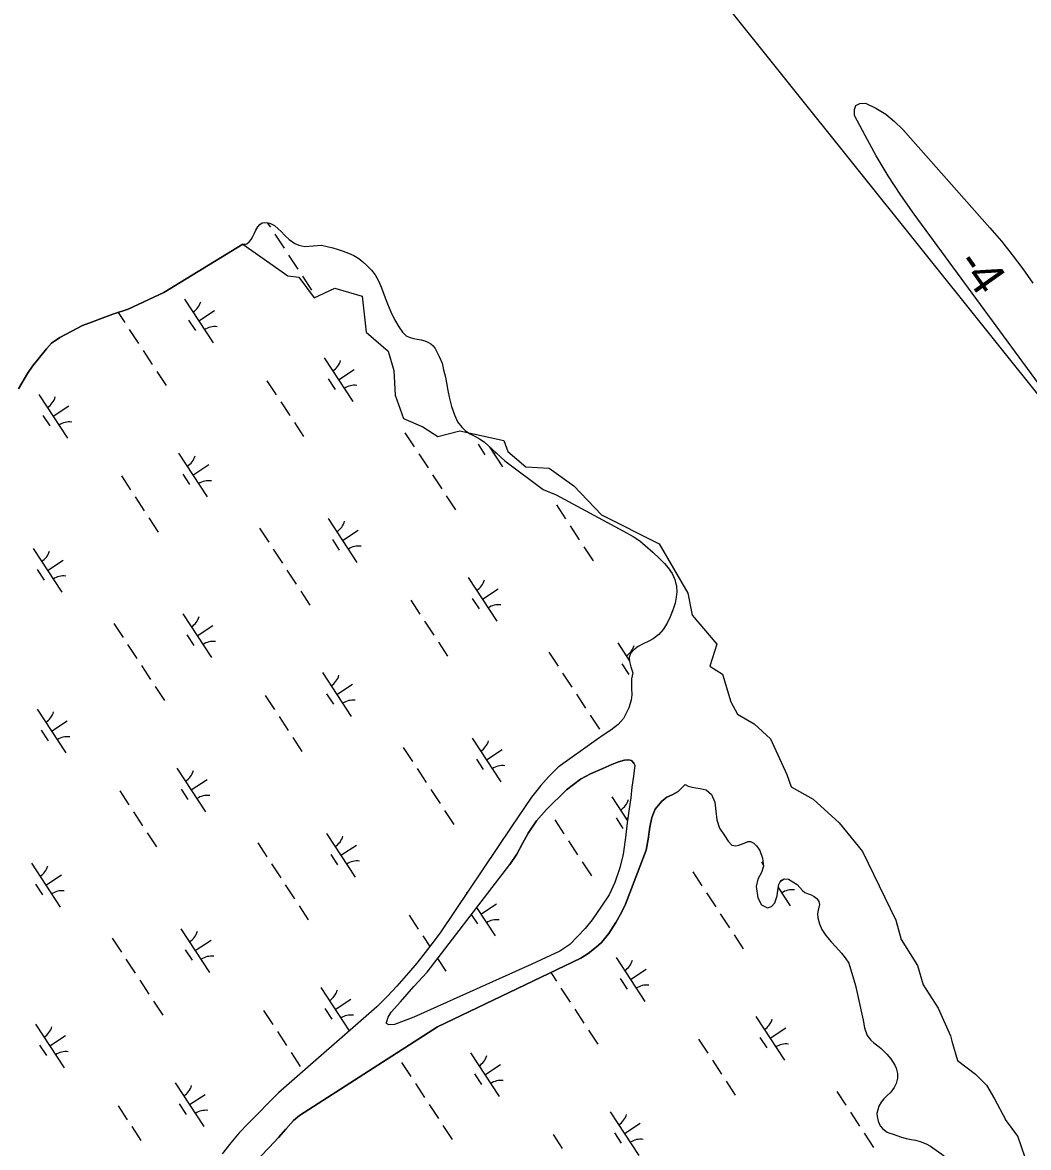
# Model space of a CAD drawing. Extents: x 3945642 to 3966284, y 206476 to 228921.
# Drawn here: x 3955515 to 3956476, y 216052 to 217128 of the extents above; entities that cross this region are included whole.
import ezdxf

# ---------------------------------------------------------------- set-up
doc = ezdxf.new("R2010")
doc.units = 0
for name, color, linetype in [('V-RIVR-EDGE', 7, 'Continuous'), ('V-RIVR-RANG', 7, 'Continuous'), ('V-TOPO-DPTH', 7, 'Continuous'), ('V-TOPO-MINR', 7, 'Continuous'), ('V-TOPO-SHOR', 7, 'Continuous'), ('V-WETL-SWMP', 7, 'Continuous')]:
    doc.layers.add(name, color=color, linetype=linetype)

msp = doc.modelspace()

# ---------------------------------------------------------------- linework, layer by layer
at = {"layer": 'V-RIVR-EDGE'}
for points in [[(3955725.2, 216916), (3955768.4, 216885.7), (3955768.4, 216885.7), (3955778.9, 216884.4), (3955793.4, 216864.6), (3955813.1, 216873.8), (3955839.4, 216866), (3955843.3, 216831.8), (3955864.3, 216813.4), (3955869.6, 216795), (3955870.9, 216771.3), (3955878.8, 216749), (3955897.2, 216741.1), (3955911.6, 216731.9), (3955932.7, 216737.2), (3955974.7, 216728), (3955978.7, 216717.5), (3955995.7, 216703), (3956018.1, 216701.7), (3956041.7, 216684.6), (3956068, 216657), (3956123.2, 216629.4), (3956150.8, 216582.1), (3956154.8, 216561.1), (3956178.4, 216533.5), (3956171.8, 216512.4), (3956183.7, 216504.6), (3956191.6, 216478.3), (3956198.1, 216466.4), (3956213.9, 216457.2), (3956229.7, 216442.8), (3956245.4, 216408.6), (3956249.4, 216396.8), (3956270.4, 216385), (3956295.4, 216362.6), (3956317.7, 216335), (3956349.3, 216269.3), (3956354.5, 216250.9), (3956370.3, 216226), (3956375.5, 216207.6), (3956390, 216185.2), (3956401.8, 216158.9), (3956403.1, 216153.7), (3956408.4, 216135.3), (3956425.5, 216122.1), (3956436, 216111.6), (3956443.9, 216098.5), (3956454.4, 216078.8)], [(3956509.6, 216035.4), (3956497, 216017.5), (3956489.8, 216000.7), (3956480.3, 216001.9), (3956468.4, 215999.6), (3956460, 215994.8), (3956476.7, 216019.8), (3956473.1, 216042.5), (3956466, 216062.8), (3956454.4, 216078.8)]]:
    msp.add_lwpolyline(points, dxfattribs=at)
at = {"layer": 'V-TOPO-DPTH'}
msp.add_line((3957463.9, 215548.9), (3955413.9, 218111.3), dxfattribs=at)
at = {"layer": 'V-TOPO-MINR'}
msp.add_lwpolyline([(3956690.9, 216503), (3956367, 216944.4), (3956354.3, 216962.6), (3956342.1, 216981.1), (3956330.8, 217000.2), (3956320.1, 217019.6), (3956310, 217039), (3956309.8, 217044.5), (3956311.2, 217048.5), (3956315, 217050.3), (3956320.4, 217050.6), (3956330.4, 217045.8), (3956339.8, 217040.1), (3956348.3, 217033.2), (3956356.3, 217025.4), (3956439.4, 216931.5), (3956450.3, 216918.8), (3956460.8, 216905.7), (3956470.8, 216892.3), (3956480.5, 216878.7)], dxfattribs=at)
at = {"layer": 'V-TOPO-SHOR'}
for points in [[(3955725.2, 216916), (3955649.9, 216869.6), (3955615.7, 216853.6), (3955601, 216848.8), (3955588.4, 216844.2), (3955581.6, 216841.7), (3955571.9, 216838.2), (3955550.4, 216826.6), (3955542.5, 216821.2), (3955537.6, 216815.8), (3955524.4, 216799.1), (3955519.6, 216792.2), (3955510.8, 216777.6)], [(3956098.1, 216505.8), (3956096.9, 216500.2), (3956096.9, 216491.2), (3956097.1, 216484.8), (3956096.4, 216479.7), (3956094.4, 216472.5), (3956089.2, 216462.4), (3956084.1, 216456.6), (3956077.1, 216451.1), (3956070.7, 216447), (3956063.4, 216441.9), (3956026.8, 216415.6), (3956017.9, 216406.8), (3956010.1, 216398.3), (3956001.2, 216387.1), (3955981.8, 216358.2), (3955914.5, 216258.4), (3955909.2, 216251), (3955899.7, 216238.4), (3955891.7, 216228.2), (3955883.8, 216219.1), (3955872.4, 216206.2), (3955863.5, 216196.8), (3955853.3, 216186.6), (3955759.4, 216104.4), (3955730.3, 216074.9), (3955721.7, 216066), (3955713.9, 216056.6), (3955705.4, 216046.1)], [(3956099.9, 216417.7), (3956098.7, 216407.1), (3956097.2, 216396.6), (3956096.1, 216386.4), (3956094.7, 216376), (3956092.8, 216362.4), (3956091, 216348.5), (3956088.8, 216332.5), (3956085.7, 216319.4), (3956081, 216305.3), (3956075.6, 216293.6), (3956067.4, 216281.7), (3956059.1, 216269.6), (3956052.6, 216261.5), (3956037.7, 216246.3), (3956028.3, 216239.8), (3956001.4, 216227.5), (3955888.6, 216176.8), (3955870.2, 216169.7), (3955864.9, 216169.4), (3955862.7, 216170.6), (3955862.6, 216171.7), (3955864.2, 216176.7), (3955867.1, 216181.3), (3955876.1, 216191.4), (3955888.8, 216205.9), (3955901.4, 216219.7), (3955980.4, 216322.8)], [(3956099.9, 216417.7), (3956099.1, 216419.6), (3956096.7, 216422.1), (3956093.9, 216422.7), (3956090.2, 216422.3), (3956084.5, 216420.7), (3956078.1, 216418.4), (3956069.5, 216414.3), (3956057.6, 216409.2), (3956048.2, 216404.1), (3956034.8, 216394.1), (3956015.4, 216375.3), (3956006, 216364.3), (3955998.1, 216352.6), (3955992.6, 216342.7), (3955987.3, 216332.4), (3955980.4, 216322.8)], [(3956148, 216399), (3956141.5, 216392.5), (3956135.6, 216389.3), (3956130.6, 216387), (3956125.7, 216383.3), (3956119.4, 216375.7), (3956116.2, 216367.6), (3956114.4, 216358.5), (3956112.8, 216346.8), (3956110.8, 216336.4), (3956091.2, 216284.8), (3956087.3, 216276.6), (3956081.9, 216267.3), (3956075, 216256.6), (3956068.1, 216248.2), (3956062.9, 216243.5), (3956055.4, 216237.7), (3956048.4, 216233.1), (3955911.4, 216167.4), (3955779.4, 216082.7), (3955773.7, 216077.8), (3955766.3, 216069.7), (3955759.4, 216061.7), (3955750.4, 216052.1), (3955742.2, 216043.4)]]:
    msp.add_lwpolyline(points, dxfattribs=at)
at = {"layer": 'V-WETL-SWMP'}
for p, q in [((3955748.7, 216936.4), (3955751.6, 216932)), ((3955756, 216925.3), (3955764.7, 216912)), ((3955769.1, 216905.3), (3955777.9, 216891.9)), ((3955782.3, 216885.2), (3955791, 216871.8)), ((3955669.5, 216863.4), (3955696.9, 216821.6)), ((3955606.1, 216850.5), (3955612.4, 216840.9)), ((3955683.2, 216842.5), (3955698.2, 216852.3)), ((3955616.8, 216834.2), (3955625.6, 216820.8)), ((3955673.4, 216843.3), (3955680, 216833.2)), ((3955630, 216814.1), (3955638.7, 216800.7)), ((3955803.1, 216807.2), (3955830.5, 216765.3)), ((3955643.1, 216794), (3955651.9, 216780.7)), ((3955816.8, 216786.2), (3955831.8, 216796.1)), ((3955748.4, 216785.3), (3955757.1, 216771.9)), ((3955807, 216787), (3955813.6, 216777)), ((3955530.3, 216772.2), (3955557.7, 216730.4)), ((3955544, 216751.3), (3955559.1, 216761.2)), ((3955761.5, 216765.2), (3955770.3, 216751.9)), ((3955534.3, 216752.1), (3955540.9, 216742.1)), ((3955774.7, 216745.2), (3955783.4, 216731.8)), ((3955880.3, 216735.5), (3955889.1, 216722.1)), ((3955663.9, 216716), (3955691.3, 216674.2)), ((3955893.5, 216715.4), (3955902.3, 216702)), ((3955950.1, 216724.5), (3955956.7, 216714.5)), ((3955960.6, 216722.5), (3955973.5, 216702.8)), ((3955677.6, 216695.1), (3955692.7, 216705)), ((3955609.2, 216694.2), (3955618, 216680.8)), ((3955667.9, 216695.9), (3955674.4, 216685.9)), ((3955906.6, 216695.3), (3955915.4, 216682)), ((3955622.4, 216674.1), (3955631.1, 216660.7)), ((3955919.8, 216675.3), (3955928.6, 216661.9)), ((3956025, 216666.6), (3956033.8, 216653.2)), ((3955635.5, 216654), (3955644.3, 216640.6)), ((3955807, 216653.5), (3955834.4, 216611.6)), ((3955741.2, 216644.3), (3955750, 216631)), ((3955820.7, 216632.6), (3955835.7, 216642.4)), ((3956038.2, 216646.5), (3956046.9, 216633.1)), ((3955810.9, 216633.3), (3955817.5, 216623.3)), ((3955524.8, 216624.9), (3955552.2, 216583)), ((3955754.3, 216624.3), (3955763.1, 216610.9)), ((3956051.3, 216626.4), (3956060.1, 216613)), ((3955538.5, 216603.9), (3955553.5, 216613.8)), ((3955528.7, 216604.7), (3955535.3, 216594.7)), ((3955767.5, 216604.2), (3955776.3, 216590.8)), ((3955940.6, 216597.2), (3955968, 216555.4)), ((3955954.3, 216576.3), (3955969.3, 216586.2)), ((3955780.6, 216584.1), (3955789.4, 216570.7)), ((3955885.9, 216575.4), (3955894.6, 216562)), ((3955944.5, 216577.1), (3955951.1, 216567.1)), ((3955667.8, 216562.3), (3955695.2, 216520.5)), ((3955899, 216555.3), (3955907.8, 216541.9)), ((3955602.1, 216553.2), (3955610.8, 216539.8)), ((3955681.5, 216541.4), (3955696.6, 216551.3)), ((3955615.2, 216533.1), (3955624, 216519.7)), ((3955671.8, 216542.2), (3955678.4, 216532.2)), ((3955912.2, 216535.3), (3955921, 216521.9)), ((3956083.6, 216534.7), (3956094.7, 216517.8)), ((3956017.9, 216525.6), (3956026.6, 216512.2)), ((3955628.4, 216513), (3955637.1, 216499.7)), ((3956087.6, 216514.6), (3956094.2, 216504.5)), ((3955801.4, 216506.1), (3955828.8, 216464.3)), ((3956031, 216505.5), (3956039.8, 216492.1)), ((3955641.5, 216493), (3955650.3, 216479.6)), ((3955815.1, 216485.2), (3955830.2, 216495)), ((3955746.7, 216484.3), (3955755.5, 216470.9)), ((3955805.4, 216486), (3955812, 216475.9)), ((3956044.2, 216485.4), (3956052.9, 216472)), ((3955528.7, 216471.2), (3955556.1, 216429.3)), ((3955542.4, 216450.3), (3955557.5, 216460.1)), ((3955759.9, 216464.2), (3955768.7, 216450.8)), ((3956057.3, 216465.3), (3956066.1, 216452)), ((3955532.7, 216451), (3955539.2, 216441)), ((3955773, 216444.1), (3955781.8, 216430.7)), ((3955944.5, 216443.5), (3955971.9, 216401.7)), ((3955878.7, 216434.4), (3955887.5, 216421)), ((3955958.2, 216422.6), (3955973.3, 216432.5)), ((3955662.3, 216414.9), (3955689.7, 216373.1)), ((3955891.9, 216414.3), (3955900.6, 216401)), ((3955948.5, 216423.4), (3955955, 216413.4)), ((3955676, 216394), (3955691.1, 216403.9)), ((3955607.6, 216393.1), (3955616.4, 216379.7)), ((3955666.3, 216394.8), (3955672.8, 216384.8)), ((3955905, 216394.3), (3955913.8, 216380.9)), ((3956078.1, 216387.3), (3956093.1, 216364.4)), ((3955620.8, 216373), (3955629.5, 216359.6)), ((3955918.2, 216374.2), (3955926.9, 216360.8)), ((3956023.4, 216365.5), (3956032.2, 216352.1)), ((3956082, 216367.2), (3956088.6, 216357.2)), ((3956091.8, 216366.4), (3956093.5, 216367.5)), ((3955633.9, 216352.9), (3955642.7, 216339.6)), ((3955805.4, 216352.4), (3955832.8, 216310.6)), ((3955739.6, 216343.3), (3955748.3, 216329.9)), ((3955819.1, 216331.5), (3955834.1, 216341.3)), ((3956036.6, 216345.4), (3956045.3, 216332)), ((3955809.3, 216332.3), (3955815.9, 216322.2)), ((3955523.2, 216323.8), (3955550.6, 216282)), ((3955752.7, 216323.2), (3955761.5, 216309.8)), ((3956049.7, 216325.3), (3956058.5, 216311.9)), ((3956221.2, 216324.8), (3956222.8, 216322.3)), ((3955536.9, 216302.9), (3955551.9, 216312.7)), ((3956155.4, 216315.7), (3956164.1, 216302.3)), ((3956239.2, 216306.7), (3956242.6, 216308.9)), ((3955527.1, 216303.7), (3955533.7, 216293.6)), ((3955765.9, 216303.1), (3955774.6, 216289.7)), ((3955939, 216296.2), (3955939.4, 216295.4)), ((3956168.5, 216295.6), (3956177.3, 216282.2)), ((3956237, 216300.6), (3956248.6, 216283)), ((3955952.7, 216275.3), (3955967.7, 216285.1)), ((3955779, 216283), (3955787.8, 216269.7)), ((3955884.3, 216274.3), (3955893, 216260.9)), ((3955943.7, 216274.9), (3955949.5, 216266)), ((3955948.6, 216281.4), (3955966.4, 216254.3)), ((3956181.7, 216275.5), (3956190.4, 216262.1)), ((3955600.4, 216252.1), (3955609.2, 216238.7)), ((3955666.2, 216261.2), (3955693.6, 216219.4)), ((3955897.4, 216254.3), (3955904.1, 216244.1)), ((3956194.8, 216255.4), (3956203.6, 216242)), ((3955679.9, 216240.3), (3955695, 216250.2)), ((3955613.6, 216232), (3955622.4, 216218.7)), ((3955670.2, 216241.1), (3955676.8, 216231.1)), ((3955911.4, 216232.9), (3955919.3, 216220.8)), ((3956082, 216233.6), (3956109.4, 216191.8)), ((3956095.7, 216212.7), (3956110.8, 216222.6)), ((3955626.7, 216212), (3955635.5, 216198.6)), ((3956019.7, 216219.3), (3956025, 216211.1)), ((3956086, 216213.5), (3956092.6, 216203.5)), ((3955799.8, 216205), (3955827, 216163.6)), ((3956029.4, 216204.4), (3956038.2, 216191)), ((3955639.9, 216191.9), (3955648.7, 216178.5)), ((3955813.5, 216184.1), (3955828.6, 216194)), ((3955745.1, 216183.2), (3955753.9, 216169.8)), ((3955803.8, 216184.9), (3955810.3, 216174.9)), ((3956042.5, 216184.4), (3956051.3, 216171)), ((3956215.6, 216177.4), (3956243, 216135.6)), ((3955527.1, 216170.1), (3955554.5, 216128.3)), ((3956229.3, 216156.5), (3956244.4, 216166.4)), ((3955540.8, 216149.2), (3955555.8, 216159)), ((3955758.3, 216163.1), (3955767, 216149.7)), ((3956055.7, 216164.3), (3956064.5, 216150.9)), ((3956160.9, 216155.6), (3956169.7, 216142.2)), ((3956219.6, 216157.3), (3956226.1, 216147.2)), ((3955531, 216150), (3955537.6, 216139.9)), ((3955771.4, 216143), (3955780.2, 216129.6)), ((3955942.9, 216142.5), (3955970.3, 216100.7)), ((3956174.1, 216135.5), (3956182.8, 216122.1)), ((3955877.1, 216133.4), (3955885.9, 216120)), ((3955956.6, 216121.6), (3955971.6, 216131.4)), ((3955660.7, 216113.9), (3955688.1, 216072)), ((3955890.2, 216113.3), (3955899, 216099.9)), ((3955946.8, 216122.4), (3955953.4, 216112.3)), ((3956187.2, 216115.4), (3956196, 216102)), ((3955674.4, 216093), (3955689.4, 216102.8)), ((3956292.9, 216105.7), (3956301.7, 216092.4)), ((3955606, 216092), (3955614.8, 216078.6)), ((3955664.6, 216093.7), (3955671.2, 216083.7)), ((3955903.4, 216093.2), (3955912.2, 216079.8)), ((3956076.5, 216086.3), (3956103.9, 216044.4)), ((3956306, 216085.7), (3956314.8, 216072.3)), ((3955619.1, 216072), (3955627.9, 216058.6)), ((3955916.5, 216073.1), (3955925.3, 216059.7)), ((3956090.2, 216065.3), (3956105.2, 216075.2)), ((3956021.8, 216064.4), (3956030.5, 216051)), ((3956080.4, 216066.1), (3956087, 216056.1)), ((3956319.2, 216065.6), (3956328, 216052.2))]:
    msp.add_line(p, q, dxfattribs=at)
for points in [[(3955510.8, 216777.6), (3955519.6, 216792.2), (3955524.4, 216799.1), (3955537.6, 216815.8), (3955542.5, 216821.2), (3955550.4, 216826.6), (3955571.9, 216838.2), (3955581.6, 216841.7), (3955588.4, 216844.2), (3955601, 216848.8), (3955615.7, 216853.6), (3955649.9, 216869.6), (3955725.2, 216916), (3955726.6, 216915.7), (3955727.7, 216915.8), (3955729.1, 216916.3), (3955731.5, 216918.1), (3955733.3, 216920.3), (3955734.8, 216923.2), (3955736, 216925.8), (3955737.7, 216929.1), (3955739.5, 216932.3), (3955741.5, 216934.7), (3955743.8, 216936.3), (3955746.2, 216936.7), (3955749.4, 216936.4), (3955751.9, 216935.6), (3955755.6, 216933.7), (3955759.2, 216930.5), (3955761.9, 216927.9), (3955765.5, 216924.2), (3955769.6, 216920.3), (3955775.1, 216916.5), (3955778.8, 216915), (3955784.5, 216913.5), (3955800.4, 216914.8), (3955811.3, 216912.2), (3955815.4, 216911), (3955821.2, 216909.1), (3955826.2, 216907.3), (3955831.5, 216905), (3955836.1, 216902), (3955840, 216898.9), (3955843.9, 216895.3), (3955848.4, 216890.9), (3955851.9, 216886.5), (3955855, 216880.8), (3955857.8, 216874), (3955860.5, 216867.2), (3955863.7, 216858.7), (3955866.9, 216851.2), (3955870.4, 216843.9), (3955874.5, 216836.9), (3955878, 216831.8), (3955881.5, 216828.3), (3955884.3, 216826.8), (3955888.3, 216825.8), (3955891.9, 216825.1), (3955895.7, 216824.5), (3955899.4, 216823.4), (3955902.7, 216821.9), (3955904.9, 216820.6), (3955907.2, 216818.5), (3955909.2, 216816.1), (3955912.9, 216808.4), (3955915.7, 216802.2), (3955917.1, 216795.8), (3955919, 216788.7), (3955920, 216783.1), (3955921.1, 216775.8), (3955922.7, 216768.3), (3955924.9, 216760.5), (3955927.6, 216752.5), (3955930.6, 216746.1), (3955934.5, 216740.9), (3955938.2, 216737.2), (3955942.5, 216734.4)], [(3955942.5, 216734.4), (3955946.4, 216732.5), (3955951.4, 216729.8), (3955955.9, 216726.9), (3955975.6, 216708.6), (3956012.4, 216681.4), (3956024.7, 216676.1), (3956089.3, 216641.4), (3956098.3, 216636.3), (3956104.9, 216632.1), (3956110, 216627.6), (3956117.1, 216621.2), (3956123.5, 216615.4), (3956128.2, 216610.6), (3956131.9, 216606.4), (3956135.6, 216600.9), (3956138.3, 216595.1), (3956139.7, 216588.5), (3956140, 216583.5), (3956139.6, 216578.3), (3956138.6, 216572.4), (3956136.7, 216566.8), (3956133.8, 216559.6), (3956130.9, 216553.5), (3956127.1, 216547.4), (3956123, 216542.6), (3956117.4, 216538.6), (3956113.3, 216536.2), (3956108.1, 216533.6), (3956103.2, 216531.1), (3956099, 216528), (3956095.9, 216524.3), (3956094.6, 216520.7), (3956094.8, 216516.7), (3956096.2, 216511.7), (3956098.1, 216505.8), (3956096.9, 216500.2), (3956096.9, 216491.2), (3956097.1, 216484.8), (3956096.4, 216479.7), (3956094.4, 216472.5), (3956089.2, 216462.4), (3956084.1, 216456.6), (3956077.1, 216451.1), (3956070.7, 216447), (3956063.4, 216441.9), (3956026.8, 216415.6), (3956017.9, 216406.8), (3956010.1, 216398.3), (3956001.2, 216387.1), (3955981.8, 216358.2), (3955914.5, 216258.4), (3955909.2, 216251), (3955899.7, 216238.4), (3955891.7, 216228.2), (3955883.8, 216219.1), (3955872.4, 216206.2), (3955863.5, 216196.8), (3955853.3, 216186.6), (3955759.4, 216104.4), (3955730.3, 216074.9), (3955721.7, 216066), (3955713.9, 216056.6), (3955705.4, 216046.1)], [(3955742.2, 216043.4), (3955750.4, 216052.1), (3955759.4, 216061.7), (3955766.3, 216069.7), (3955773.7, 216077.8), (3955779.4, 216082.7), (3955911.4, 216167.4), (3956048.4, 216233.1), (3956055.4, 216237.7), (3956062.9, 216243.5), (3956068.1, 216248.2), (3956075, 216256.6), (3956081.9, 216267.3), (3956087.3, 216276.6), (3956091.2, 216284.8), (3956110.8, 216336.4), (3956112.8, 216346.8), (3956114.4, 216358.5), (3956116.2, 216367.6), (3956119.4, 216375.7), (3956125.7, 216383.3), (3956130.6, 216387), (3956135.6, 216389.3), (3956141.5, 216392.5), (3956148, 216399), (3956151.1, 216397.5), (3956154.7, 216396.7), (3956158.4, 216396.1), (3956162.4, 216395.4), (3956168.3, 216393.9), (3956173.4, 216389.7), (3956176.3, 216382.4), (3956177.4, 216373.8), (3956178.4, 216365.3), (3956180.8, 216357.5), (3956185.8, 216350.5), (3956189.1, 216345.1), (3956192.7, 216341.2), (3956196.4, 216340.4), (3956199.4, 216341.3), (3956204.4, 216343.1), (3956208.2, 216344.7), (3956210.6, 216344.6), (3956213.6, 216343.2), (3956216.3, 216340.6), (3956219.4, 216336), (3956222.1, 216328.7), (3956222.9, 216321.1), (3956221.2, 216315.1), (3956217.6, 216308.6), (3956215.9, 216301.6), (3956217.4, 216290.8), (3956220.9, 216284.2), (3956226.7, 216281.3), (3956230.6, 216282.5), (3956233.9, 216286), (3956236, 216292.6), (3956236.6, 216298), (3956237.5, 216303.5), (3956239.6, 216307.5), (3956242.9, 216309.1), (3956247, 216308.5), (3956255.1, 216303.4), (3956260.2, 216297.7), (3956262.5, 216295.9), (3956265.8, 216294.7), (3956268, 216293.9), (3956271.4, 216292.1), (3956274.1, 216290.3), (3956275.9, 216287.4), (3956276.4, 216284.3), (3956275.2, 216278.9), (3956274.5, 216275.4), (3956274.8, 216271.6), (3956276.4, 216265.9), (3956278.8, 216260.6), (3956282.6, 216254.9), (3956287.8, 216248.8), (3956292.1, 216243.8), (3956297.4, 216237.9), (3956301.1, 216233.5), (3956304.4, 216228.2), (3956311, 216207), (3956318.2, 216173.8), (3956319.5, 216166.5), (3956322.2, 216159.2), (3956325.5, 216154.7), (3956328.4, 216152.1), (3956332.2, 216149.2), (3956335.3, 216146.8), (3956340.9, 216141.2), (3956344.6, 216136.7), (3956348.5, 216130.7), (3956349.7, 216127.8), (3956350.9, 216122.8), (3956351, 216118.2), (3956349.9, 216113.3), (3956347.9, 216109.3), (3956344.8, 216105), (3956340.9, 216101.4), (3956337.9, 216098.7)], [(3956337.9, 216098.7), (3956335.3, 216095.5), (3956333.1, 216091.7), (3956331.4, 216084.5), (3956331.6, 216081.6), (3956332.5, 216077.1), (3956334.4, 216072.6), (3956336.7, 216070.2), (3956338.5, 216068.7), (3956341.1, 216066.8), (3956342.8, 216066.2), (3956346.9, 216064.8), (3956354, 216062.3), (3956359.2, 216060.8), (3956364, 216059.8), (3956368.4, 216059), (3956372.6, 216057.8), (3956378.3, 216055.7), (3956382.7, 216053.2), (3956395.6, 216044.1)]]:
    msp.add_lwpolyline(points, dxfattribs=at)
msp.add_lwpolyline([(3955980.4, 216322.8), (3955987.3, 216332.4), (3955992.6, 216342.7), (3955998.1, 216352.6), (3956006, 216364.3), (3956015.4, 216375.3), (3956034.8, 216394.1), (3956048.2, 216404.1), (3956057.6, 216409.2), (3956069.5, 216414.3), (3956078.1, 216418.4), (3956084.5, 216420.7), (3956090.2, 216422.3), (3956093.9, 216422.7), (3956096.7, 216422.1), (3956099.1, 216419.6), (3956099.9, 216417.7), (3956098.7, 216407.1), (3956097.2, 216396.6), (3956096.1, 216386.4), (3956094.7, 216376), (3956092.8, 216362.4), (3956091, 216348.5), (3956088.8, 216332.5), (3956085.7, 216319.4), (3956081, 216305.3), (3956075.6, 216293.6), (3956067.4, 216281.7), (3956059.1, 216269.6), (3956052.6, 216261.5), (3956037.7, 216246.3), (3956028.3, 216239.8), (3956001.4, 216227.5), (3955888.6, 216176.8), (3955870.2, 216169.7), (3955864.9, 216169.4), (3955862.7, 216170.6), (3955862.6, 216171.7), (3955864.2, 216176.7), (3955867.1, 216181.3), (3955876.1, 216191.4), (3955888.8, 216205.9), (3955901.4, 216219.7)], close=True, dxfattribs=at)
for centre, start, end in [((3955668.2, 216865.7), 302.4575, 344.0011), ((3955698.5, 216819.5), 82.4574, 124.0011), ((3955801.8, 216809.5), 302.4575, 344.0011), ((3955832.1, 216763.3), 82.4574, 124.0011), ((3955529.1, 216774.6), 302.4575, 344.0011), ((3955559.4, 216728.3), 82.4574, 124.0011), ((3955975.2, 216700.7), 116.9446, 124.0011), ((3955662.7, 216718.3), 302.4575, 344.0011), ((3955692.9, 216672.1), 82.4574, 124.0011), ((3955805.7, 216655.8), 302.4575, 344.0011), ((3955523.5, 216627.2), 302.4575, 344.0011), ((3955836, 216609.6), 82.4574, 124.0011), ((3955553.8, 216581), 82.4574, 124.0011), ((3955939.3, 216599.6), 302.4575, 344.0011), ((3955969.6, 216553.4), 82.4574, 124.0011), ((3955666.6, 216564.6), 302.4575, 344.0011), ((3955696.9, 216518.4), 82.4574, 124.0011), ((3956082.4, 216537), 302.4575, 344.0011), ((3955800.2, 216508.4), 302.4575, 344.0011), ((3955830.5, 216462.2), 82.4574, 124.0011), ((3955527.5, 216473.5), 302.4575, 344.0011), ((3955557.7, 216427.3), 82.4574, 124.0011), ((3955943.3, 216445.9), 302.4575, 344.0011), ((3955973.5, 216399.7), 82.4574, 124.0011), ((3955661.1, 216417.3), 302.4575, 344.0011), ((3955691.3, 216371.1), 82.4574, 124.0011), ((3956076.9, 216389.6), 302.4575, 344.0011), ((3955804.1, 216354.7), 302.4575, 344.0011), ((3955521.9, 216326.1), 302.4575, 344.0011), ((3955834.4, 216308.5), 82.4574, 124.0011), ((3955552.2, 216279.9), 82.4574, 124.0011), ((3956250.2, 216280.9), 82.4574, 124.0011), ((3955968, 216252.3), 82.4574, 124.0011), ((3955665, 216263.6), 302.4575, 344.0011), ((3955695.3, 216217.4), 82.4574, 124.0011), ((3956080.8, 216236), 302.4575, 344.0011), ((3955798.6, 216207.3), 302.4575, 344.0011), ((3956111.1, 216189.7), 82.4574, 124.0011), ((3955828.8, 216161.1), 82.4574, 124.0011), ((3955525.9, 216172.4), 302.4575, 344.0011), ((3956214.4, 216179.7), 302.4575, 344.0011), ((3956244.6, 216133.5), 82.4574, 124.0011), ((3955556.1, 216126.2), 82.4574, 124.0011), ((3955941.6, 216144.8), 302.4575, 344.0011), ((3955971.9, 216098.6), 82.4574, 124.0011), ((3955659.4, 216116.2), 302.4575, 344.0011), ((3955689.7, 216070), 82.4574, 124.0011), ((3956075.2, 216088.6), 302.4575, 344.0011), ((3956105.5, 216042.4), 82.4574, 124.0011)]:
    msp.add_arc(centre, 17.6, start, end, dxfattribs=at)

# ---------------------------------------------------------------- texts
at = {"layer": 'V-RIVR-RANG'}
msp.add_text('-4', height=33.5, rotation=305.2748, dxfattribs=at).set_placement((3956406.4, 216897.4))

doc.saveas('drawing.dxf')
